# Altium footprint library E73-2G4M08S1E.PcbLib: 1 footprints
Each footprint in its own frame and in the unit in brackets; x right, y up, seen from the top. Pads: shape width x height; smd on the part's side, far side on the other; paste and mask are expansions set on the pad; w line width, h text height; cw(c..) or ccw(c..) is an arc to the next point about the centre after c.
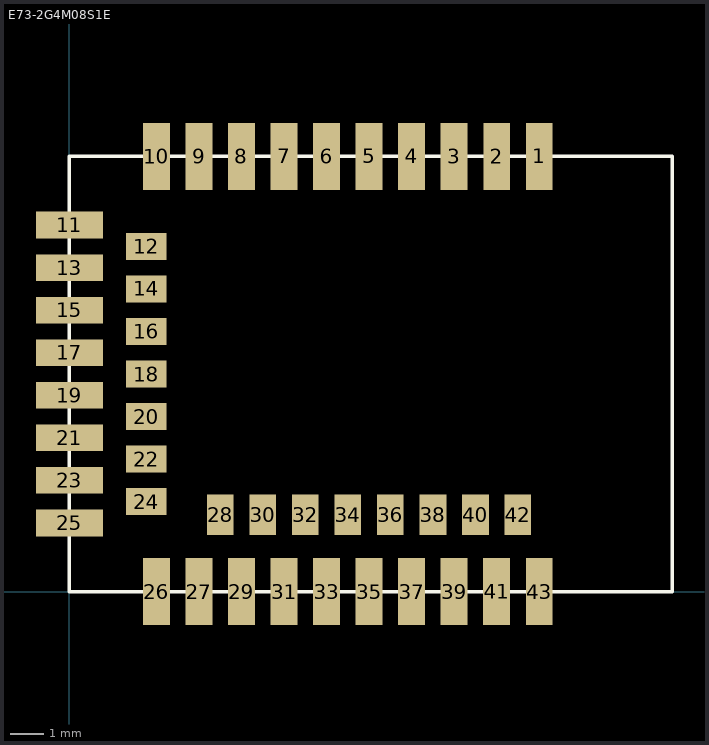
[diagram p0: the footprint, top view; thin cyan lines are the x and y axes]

## E73-2G4M08S1E [mm]
pads (43):
  rect 0.8x2 smd: 1(14.03,13) 2(12.76,13) 3(11.49,13) 4(10.22,13) 5(8.95,13) 6(7.68,13) 7(6.41,13) 8(5.14,13) 9(3.873,13) 10(2.6,13) 26(2.6,0) 27(3.87,0) 29(5.14,0) 31(6.41,0) 33(7.68,0) 35(8.95,0) 37(10.22,0) 39(11.49,0) 41(12.757,0) 43(14.03,0)
  rect 2x0.8 smd: 11(0,10.945) 13(0,9.675) 15(0,8.405) 17(0,7.135) 19(0,5.865) 21(0,4.595) 23(0,3.325) 25(0,2.055)
  rect 1.2x0.8 smd: 12(2.3,10.31) 14(2.3,9.04) 16(2.3,7.77) 18(2.3,6.5) 20(2.3,5.23) 22(2.3,3.96) 24(2.3,2.69)
  rect 0.8x1.2 smd: 28(4.505,2.3) 30(5.775,2.3) 32(7.045,2.3) 34(8.315,2.3) 36(9.585,2.3) 38(10.855,2.3) 40(12.125,2.3) 42(13.39,2.3)
Top Overlay:
  lines w0.1: 0,0 0,13 18,13 18,0 0,0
